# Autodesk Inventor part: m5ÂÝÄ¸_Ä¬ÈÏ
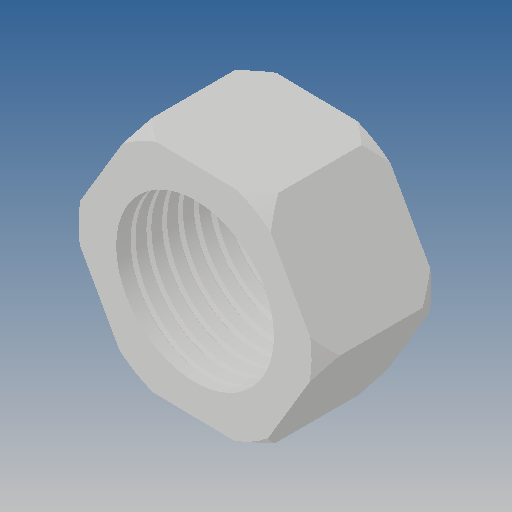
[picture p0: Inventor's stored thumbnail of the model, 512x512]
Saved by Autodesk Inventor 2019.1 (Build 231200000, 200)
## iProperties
Created: 2012-10
Part Number: m5ÂÝÄ¸_Ä¬ÈÏ
Material: Ogólny
Document SubType Name: Modeling
Designer: CADENGINEERING4
Density: 1 g/cm^3
Appearance: Domyślna
Author: CADENGINEERING4
Revision Number: ÈÎºÎ
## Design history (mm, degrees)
feature "NONE"
node "Bryła1"
